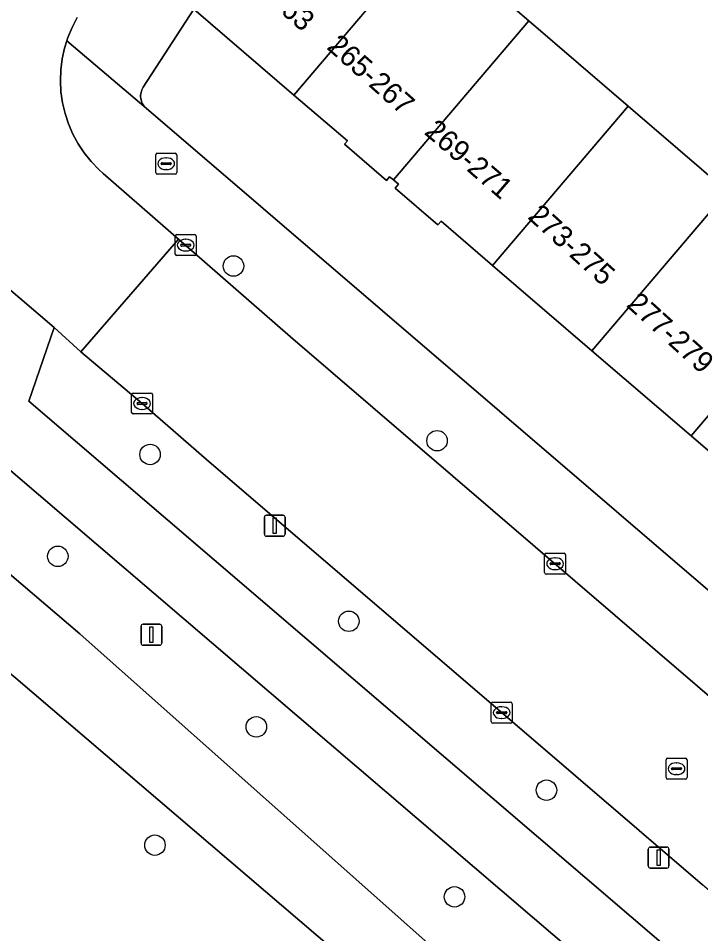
# Model space of a CAD drawing. Extents: x 159279 to 160377, y 384531 to 385888.
# Drawn here: x 159802.17 to 159834.73, y 384749.19 to 384792.89 of the extents above; entities that cross this region are included whole.
import ezdxf

# ---------------------------------------------------------------- set-up
doc = ezdxf.new("R2010")
doc.units = 0
for name, color, linetype in [('IMGEO_Berm_groen', 7, 'Continuous'), ('IMGEO_Boom', 7, 'Continuous'), ('IMGEO_Brandkraan', 7, 'Continuous'), ('IMGEO_Erf', 7, 'Continuous'), ('IMGEO_Fietspad_open', 7, 'Continuous'), ('IMGEO_Groenvoorziening', 7, 'Continuous'), ('IMGEO_Kolk', 7, 'Continuous'), ('IMGEO_Lichtmast', 7, 'Continuous'), ('IMGEO_Pand', 7, 'Continuous'), ('IMGEO_Pand_nummerreeks', 7, 'Continuous'), ('IMGEO_Rijbaan_lokaal_open', 7, 'Continuous'), ('IMGEO_Rioolput', 7, 'Continuous'), ('IMGEO_Voetpad_halfverhard', 7, 'Continuous'), ('IMGEO_Voetpad_open', 7, 'Continuous')]:
    doc.layers.add(name, color=color, linetype=linetype)

msp = doc.modelspace()

# ---------------------------------------------------------------- linework, layer by layer
at = {"layer": 'IMGEO_Berm_groen'}
for points in [[(159822.73, 384761.9), (159811.286, 384771.727), (159808.08, 384774.505), (159805.152, 384776.974), (159803.886, 384778.134), (159802.682, 384774.612), (159831.413, 384750), (159855.982, 384728.954), (159858.25, 384731.558), (159847.676, 384740.593), (159836.596, 384750), (159834.815, 384751.53)], [(159801.703, 384771.392), (159800.659, 384767.301), (159805.116, 384763.503), (159825.6, 384745.284), (159848.632, 384726.205), (159851.029, 384723.93), (159853.776, 384726.823), (159826.697, 384750)]]:
    msp.add_lwpolyline(points, close=True, dxfattribs=at)
at = {"layer": 'IMGEO_Boom'}
for centre in [(159812.439, 384781.067), (159822.155, 384772.728), (159808.461, 384772.07), (159804.058, 384767.208), (159817.943, 384764.108), (159813.53, 384759.068), (159827.376, 384756.044), (159808.692, 384753.42), (159822.989, 384750.954)]:
    msp.add_circle(centre, 0.489, dxfattribs=at)
at = {"layer": 'IMGEO_Brandkraan'}
for p, q in [((159808.73, 384785.526), (159808.73, 384786.378)), ((159808.805, 384786.452), (159809.657, 384786.452)), ((159809.218, 384786.232), (159809.243, 384786.232)), ((159809.731, 384786.378), (159809.731, 384785.526)), ((159808.989, 384785.946), (159808.989, 384785.958)), ((159809.427, 384785.909), (159809.029, 384785.909)), ((159809.032, 384785.995), (159809.43, 384785.995)), ((159809.473, 384785.958), (159809.473, 384785.946)), ((159809.657, 384785.452), (159808.805, 384785.452)), ((159809.241, 384785.672), (159809.216, 384785.672))]:
    msp.add_line(p, q, dxfattribs=at)
for points in [[(159808.73, 384785.526), (159808.73, 384786.378)], [(159808.805, 384786.452), (159809.657, 384786.452)], [(159809.731, 384786.378), (159809.731, 384785.526)], [(159809.657, 384785.452), (159808.805, 384785.452)]]:
    msp.add_lwpolyline(points, dxfattribs=at)
for centre, radius, start, end in [((159808.807, 384786.376), 0.0765, 91.552, 178.448), ((159808.807, 384786.376), 0.0765, 91.552, 178.448), ((159809.655, 384786.376), 0.0765, 1.552, 88.448), ((159809.655, 384786.376), 0.0765, 1.552, 88.448), ((159809.029, 384785.955), 0.0403, 85.8775, 175.7526), ((159809.026, 384785.945), 0.0366, 178.938, 274.7102), ((159809.43, 384785.952), 0.043, 264.8664, 352.4533), ((159809.434, 384785.957), 0.0386, 1.7309, 96.639), ((159808.807, 384785.528), 0.0765, 181.552, 268.448), ((159808.807, 384785.528), 0.0765, 181.552, 268.448), ((159809.655, 384785.528), 0.0765, 271.552, 358.448), ((159809.655, 384785.528), 0.0765, 271.552, 358.448)]:
    msp.add_arc(centre, radius, start, end, dxfattribs=at)
for centre, major_axis, ratio, start_param, end_param in [((159809.217, 384785.952), (-0.387, 0.002), 0.722429, 4.712389, 7.853982), ((159809.242, 384785.952), (-0.39, 0.002), 0.717154, 1.570796, 4.712389)]:
    msp.add_ellipse(centre, major_axis=major_axis, ratio=ratio, start_param=start_param, end_param=end_param, dxfattribs=at)
at = {"layer": 'IMGEO_Erf'}
for points in [[(159814.594, 384798.937), (159815.059, 384798.586), (159817.054, 384800.909), (159821.793, 384796.841), (159826.532, 384792.771), (159831.272, 384788.701), (159836.012, 384784.631), (159840.752, 384780.562), (159845.492, 384776.492), (159850.232, 384772.422), (159854.972, 384768.352), (159859.712, 384764.282), (159864.451, 384760.212), (159869.191, 384756.142), (159873.931, 384752.073), (159876.345, 384750), (159878.671, 384748.003), (159883.411, 384743.933), (159885.124, 384744.266), (159889.352, 384746.225), (159896.887, 384757.365), (159896.975, 384757.494), (159822.578, 384807.809)], [(159836.743, 384770.844), (159834.286, 384772.954), (159829.546, 384777.024), (159824.806, 384781.094), (159822.348, 384783.205), (159822.199, 384783.032), (159820.151, 384784.791), (159820.308, 384784.974), (159820.075, 384785.174), (159819.893, 384785.331), (159819.742, 384785.156), (159817.736, 384786.878), (159817.874, 384787.038), (159815.322, 384789.229), (159810.546, 384793.33), (159808.139, 384789.601), (159808.104, 384789.542), (159808.074, 384789.48), (159808.049, 384789.416), (159808.031, 384789.349), (159808.019, 384789.282), (159808.012, 384789.213), (159808.012, 384789.144), (159808.018, 384789.076), (159808.03, 384789.008), (159808.048, 384788.942), (159808.072, 384788.877), (159808.102, 384788.815), (159808.137, 384788.756), (159808.177, 384788.7), (159808.222, 384788.648), (159808.268, 384788.603), (159853.266, 384750)]]:
    msp.add_lwpolyline(points, dxfattribs=at)
at = {"layer": 'IMGEO_Fietspad_open'}
msp.add_lwpolyline([(159859.416, 384726.013), (159855.982, 384728.954), (159831.413, 384750), (159802.682, 384774.612), (159803.886, 384778.134), (159800.589, 384780.925), (159799.437, 384777.363), (159788.614, 384786.662), (159790.807, 384789.238), (159787.819, 384791.8), (159785.571, 384789.272), (159783.746, 384786.801), (159786.896, 384784.107), (159798.413, 384774.215), (159798.491, 384774.148), (159801.703, 384771.392), (159826.697, 384750), (159853.776, 384726.823), (159857.499, 384723.68)], dxfattribs=at)
at = {"layer": 'IMGEO_Groenvoorziening'}
msp.add_lwpolyline([(159845.317, 384724.65), (159823.259, 384743.264), (159802.05, 384761.39), (159798.105, 384764.665), (159786.804, 384735.881), (159794.418, 384727.063), (159801.729, 384733.387), (159801.507, 384733.655), (159805.787, 384737.392), (159806.023, 384737.131), (159813.731, 384743.883), (159824.896, 384730.93), (159824.445, 384730.535), (159827.058, 384727.504), (159827.511, 384727.898), (159837.427, 384716.393)], dxfattribs=at)
at = {"layer": 'IMGEO_Kolk'}
for p, q in [((159809.661, 384781.638), (159809.661, 384782.49)), ((159809.736, 384782.564), (159810.588, 384782.564)), ((159810.149, 384782.344), (159810.174, 384782.344)), ((159810.662, 384782.49), (159810.662, 384781.638)), ((159809.92, 384782.058), (159809.92, 384782.07)), ((159810.358, 384782.021), (159809.96, 384782.021)), ((159809.963, 384782.107), (159810.361, 384782.107)), ((159810.404, 384782.07), (159810.404, 384782.058)), ((159810.588, 384781.564), (159809.736, 384781.564)), ((159810.172, 384781.784), (159810.147, 384781.784)), ((159807.578, 384774.078), (159807.578, 384774.93)), ((159807.653, 384775.004), (159808.505, 384775.004)), ((159808.579, 384774.93), (159808.579, 384774.078)), ((159807.837, 384774.498), (159807.837, 384774.51)), ((159808.275, 384774.461), (159807.877, 384774.461)), ((159807.88, 384774.547), (159808.278, 384774.547)), ((159808.066, 384774.784), (159808.091, 384774.784)), ((159808.321, 384774.51), (159808.321, 384774.498)), ((159808.505, 384774.004), (159807.653, 384774.004)), ((159808.089, 384774.224), (159808.064, 384774.224)), ((159827.286, 384766.43), (159827.286, 384767.282)), ((159827.361, 384767.356), (159828.213, 384767.356)), ((159827.774, 384767.136), (159827.799, 384767.136)), ((159828.287, 384767.282), (159828.287, 384766.43)), ((159827.545, 384766.85), (159827.545, 384766.862)), ((159827.983, 384766.813), (159827.585, 384766.813)), ((159827.588, 384766.899), (159827.986, 384766.899)), ((159827.797, 384766.576), (159827.772, 384766.576)), ((159828.029, 384766.862), (159828.029, 384766.85)), ((159828.213, 384766.356), (159827.361, 384766.356)), ((159824.738, 384759.32), (159824.738, 384760.172)), ((159824.813, 384760.246), (159825.665, 384760.246)), ((159825.226, 384760.026), (159825.251, 384760.026)), ((159825.739, 384760.172), (159825.739, 384759.32)), ((159824.997, 384759.74), (159824.997, 384759.752)), ((159825.435, 384759.703), (159825.037, 384759.703)), ((159825.04, 384759.789), (159825.438, 384759.789)), ((159825.481, 384759.752), (159825.481, 384759.74)), ((159825.665, 384759.246), (159824.813, 384759.246)), ((159825.249, 384759.466), (159825.224, 384759.466))]:
    msp.add_line(p, q, dxfattribs=at)
for points in [[(159809.661, 384781.638), (159809.661, 384782.49)], [(159809.736, 384782.564), (159810.588, 384782.564)], [(159810.662, 384782.49), (159810.662, 384781.638)], [(159810.588, 384781.564), (159809.736, 384781.564)], [(159807.578, 384774.078), (159807.578, 384774.93)], [(159807.653, 384775.004), (159808.505, 384775.004)], [(159808.579, 384774.93), (159808.579, 384774.078)], [(159808.505, 384774.004), (159807.653, 384774.004)], [(159827.286, 384766.43), (159827.286, 384767.282)], [(159827.361, 384767.356), (159828.213, 384767.356)], [(159828.287, 384767.282), (159828.287, 384766.43)], [(159828.213, 384766.356), (159827.361, 384766.356)], [(159824.738, 384759.32), (159824.738, 384760.172)], [(159824.813, 384760.246), (159825.665, 384760.246)], [(159825.739, 384760.172), (159825.739, 384759.32)], [(159825.665, 384759.246), (159824.813, 384759.246)]]:
    msp.add_lwpolyline(points, dxfattribs=at)
for centre, radius, start, end in [((159809.738, 384782.488), 0.0765, 91.552, 178.448), ((159809.738, 384782.488), 0.0765, 91.552, 178.448), ((159810.586, 384782.488), 0.0765, 1.552, 88.448), ((159810.586, 384782.488), 0.0765, 1.552, 88.448), ((159809.96, 384782.067), 0.0403, 85.8775, 175.7526), ((159809.957, 384782.057), 0.0366, 178.938, 274.7102), ((159810.361, 384782.064), 0.043, 264.8664, 352.4533), ((159810.365, 384782.069), 0.0386, 1.7309, 96.639), ((159809.738, 384781.64), 0.0765, 181.552, 268.448), ((159809.738, 384781.64), 0.0765, 181.552, 268.448), ((159810.586, 384781.64), 0.0765, 271.552, 358.448), ((159810.586, 384781.64), 0.0765, 271.552, 358.448), ((159807.655, 384774.928), 0.0765, 91.552, 178.448), ((159807.655, 384774.928), 0.0765, 91.552, 178.448), ((159808.503, 384774.928), 0.0765, 1.552, 88.448), ((159808.503, 384774.928), 0.0765, 1.552, 88.448), ((159807.877, 384774.507), 0.0403, 85.8775, 175.7526), ((159807.874, 384774.497), 0.0366, 178.938, 274.7102), ((159808.278, 384774.504), 0.043, 264.8664, 352.4533), ((159808.282, 384774.509), 0.0386, 1.7309, 96.639), ((159807.655, 384774.08), 0.0765, 181.552, 268.448), ((159807.655, 384774.08), 0.0765, 181.552, 268.448), ((159808.503, 384774.08), 0.0765, 271.552, 358.448), ((159808.503, 384774.08), 0.0765, 271.552, 358.448), ((159827.363, 384767.28), 0.0765, 91.552, 178.448), ((159827.363, 384767.28), 0.0765, 91.552, 178.448), ((159828.211, 384767.28), 0.0765, 1.552, 88.448), ((159828.211, 384767.28), 0.0765, 1.552, 88.448), ((159827.585, 384766.859), 0.0403, 85.8775, 175.7526), ((159827.582, 384766.849), 0.0366, 178.938, 274.7102), ((159827.986, 384766.856), 0.043, 264.8664, 352.4533), ((159827.99, 384766.861), 0.0386, 1.7309, 96.639), ((159827.363, 384766.432), 0.0765, 181.552, 268.448), ((159827.363, 384766.432), 0.0765, 181.552, 268.448), ((159828.211, 384766.432), 0.0765, 271.552, 358.448), ((159828.211, 384766.432), 0.0765, 271.552, 358.448), ((159824.815, 384760.17), 0.0765, 91.552, 178.448), ((159824.815, 384760.17), 0.0765, 91.552, 178.448), ((159825.663, 384760.17), 0.0765, 1.552, 88.448), ((159825.663, 384760.17), 0.0765, 1.552, 88.448), ((159825.037, 384759.749), 0.0403, 85.8775, 175.7526), ((159825.034, 384759.739), 0.0366, 178.938, 274.7102), ((159825.438, 384759.746), 0.043, 264.8664, 352.4533), ((159825.442, 384759.751), 0.0386, 1.7309, 96.639), ((159824.815, 384759.322), 0.0765, 181.552, 268.448), ((159824.815, 384759.322), 0.0765, 181.552, 268.448), ((159825.663, 384759.322), 0.0765, 271.552, 358.448), ((159825.663, 384759.322), 0.0765, 271.552, 358.448)]:
    msp.add_arc(centre, radius, start, end, dxfattribs=at)
for centre, major_axis, ratio, start_param, end_param in [((159810.148, 384782.064), (-0.387, 0.002), 0.722429, 4.712389, 7.853982), ((159810.173, 384782.064), (-0.39, 0.002), 0.717154, 1.570796, 4.712389), ((159808.065, 384774.504), (-0.387, 0.002), 0.722429, 4.712389, 7.853982), ((159808.09, 384774.504), (-0.39, 0.002), 0.717154, 1.570796, 4.712389), ((159827.773, 384766.856), (-0.387, 0.002), 0.722429, 4.712389, 7.853982), ((159827.798, 384766.856), (-0.39, 0.002), 0.717154, 1.570796, 4.712389), ((159825.225, 384759.746), (-0.387, 0.002), 0.722429, 4.712389, 7.853982), ((159825.25, 384759.746), (-0.39, 0.002), 0.717154, 1.570796, 4.712389)]:
    msp.add_ellipse(centre, major_axis=major_axis, ratio=ratio, start_param=start_param, end_param=end_param, dxfattribs=at)
at = {"layer": 'IMGEO_Lichtmast'}
for p, q in [((159814.015, 384769.171), (159814.805, 384769.171)), ((159814.805, 384769.171), (159814.015, 384769.171)), ((159813.915, 384768.271), (159813.915, 384769.071)), ((159813.915, 384769.071), (159813.915, 384768.271)), ((159814.905, 384769.071), (159814.905, 384768.271)), ((159814.905, 384768.271), (159814.905, 384769.071)), ((159814.805, 384768.171), (159814.015, 384768.171)), ((159814.015, 384768.171), (159814.805, 384768.171)), ((159808.129, 384763.967), (159808.919, 384763.967)), ((159808.919, 384763.967), (159808.129, 384763.967)), ((159808.029, 384763.067), (159808.029, 384763.867)), ((159808.029, 384763.867), (159808.029, 384763.067)), ((159809.019, 384763.867), (159809.019, 384763.067)), ((159809.019, 384763.067), (159809.019, 384763.867)), ((159808.919, 384762.967), (159808.129, 384762.967)), ((159808.129, 384762.967), (159808.919, 384762.967)), ((159832.23, 384752.427), (159832.23, 384753.227)), ((159832.23, 384753.227), (159832.23, 384752.427)), ((159832.33, 384753.327), (159833.12, 384753.327)), ((159833.12, 384753.327), (159832.33, 384753.327)), ((159833.22, 384753.227), (159833.22, 384752.427)), ((159833.22, 384752.427), (159833.22, 384753.227)), ((159833.12, 384752.327), (159832.33, 384752.327)), ((159832.33, 384752.327), (159833.12, 384752.327))]:
    msp.add_line(p, q, dxfattribs=at)
for points in [[(159814.335, 384769.046), (159814.485, 384769.046), (159814.485, 384768.296), (159814.335, 384768.296), (159814.335, 384769.046)], [(159808.449, 384763.842), (159808.599, 384763.842), (159808.599, 384763.092), (159808.449, 384763.092), (159808.449, 384763.842)], [(159832.65, 384753.202), (159832.8, 384753.202), (159832.8, 384752.452), (159832.65, 384752.452), (159832.65, 384753.202)]]:
    msp.add_lwpolyline(points, dxfattribs=at)
for centre, start, end in [((159814.015, 384769.071), 90, 180), ((159814.015, 384769.071), 90, 180), ((159814.805, 384769.071), 0, 90), ((159814.805, 384769.071), 360, 90), ((159814.015, 384768.271), 180, 270), ((159814.015, 384768.271), 180, 270), ((159814.805, 384768.271), 270, 0), ((159814.805, 384768.271), 270, 0), ((159808.129, 384763.867), 90, 180), ((159808.129, 384763.867), 90, 180), ((159808.919, 384763.867), 0, 90), ((159808.919, 384763.867), 360, 90), ((159808.129, 384763.067), 180, 270), ((159808.129, 384763.067), 180, 270), ((159808.919, 384763.067), 270, 0), ((159808.919, 384763.067), 270, 0), ((159832.33, 384753.227), 90, 180), ((159832.33, 384753.227), 90, 180), ((159833.12, 384753.227), 0, 90), ((159833.12, 384753.227), 360, 90), ((159832.33, 384752.427), 180, 270), ((159832.33, 384752.427), 180, 270), ((159833.12, 384752.427), 270, 0), ((159833.12, 384752.427), 270, 0)]:
    msp.add_arc(centre, 0.1, start, end, dxfattribs=at)
at = {"layer": 'IMGEO_Pand'}
for points in [[(159815.322, 384789.229), (159821.793, 384796.841), (159817.054, 384800.909), (159815.059, 384798.586), (159810.546, 384793.33)], [(159817.874, 384787.038), (159817.736, 384786.878), (159819.742, 384785.156), (159819.893, 384785.331), (159820.075, 384785.174), (159826.532, 384792.771), (159821.793, 384796.841), (159815.322, 384789.229)], [(159826.532, 384792.771), (159820.075, 384785.174), (159820.308, 384784.974), (159820.151, 384784.791), (159822.199, 384783.032), (159822.348, 384783.205), (159824.806, 384781.094), (159831.272, 384788.701)], [(159829.546, 384777.024), (159836.012, 384784.631), (159831.272, 384788.701), (159824.806, 384781.094)], [(159836.012, 384784.631), (159829.546, 384777.024), (159834.286, 384772.954), (159840.752, 384780.562)], [(159840.752, 384780.562), (159834.286, 384772.954), (159836.743, 384770.844), (159836.604, 384770.683), (159838.626, 384768.947), (159838.763, 384769.107), (159839.024, 384768.882), (159845.492, 384776.492)]]:
    msp.add_lwpolyline(points, close=True, dxfattribs=at)
at = {"layer": 'IMGEO_Rijbaan_lokaal_open'}
for points in [[(159800.589, 384780.925), (159803.886, 384778.134), (159805.152, 384776.974), (159809.818, 384782.351), (159806.227, 384785.489), (159806.016, 384785.68), (159805.651, 384786.059), (159805.321, 384786.469), (159805.029, 384786.907), (159804.777, 384787.369), (159804.567, 384787.852), (159804.402, 384788.352), (159804.282, 384788.864), (159804.208, 384789.385), (159804.181, 384789.911), (159804.201, 384790.437), (159804.267, 384790.959), (159804.381, 384791.473), (159804.488, 384791.813), (159804.539, 384791.975), (159804.742, 384792.461), (159804.988, 384792.926)], [(159836.494, 384759.376), (159815.158, 384777.694), (159809.818, 384782.351), (159805.152, 384776.974), (159808.08, 384774.505), (159811.286, 384771.727), (159822.73, 384761.9), (159834.815, 384751.53)]]:
    msp.add_lwpolyline(points, dxfattribs=at)
at = {"layer": 'IMGEO_Rioolput'}
for p, q in [((159833.083, 384756.643), (159833.083, 384757.495)), ((159833.158, 384757.569), (159834.01, 384757.569)), ((159833.571, 384757.349), (159833.596, 384757.349)), ((159834.084, 384757.495), (159834.084, 384756.643)), ((159833.342, 384757.063), (159833.342, 384757.075)), ((159833.78, 384757.026), (159833.382, 384757.026)), ((159833.385, 384757.112), (159833.783, 384757.112)), ((159833.826, 384757.075), (159833.826, 384757.063)), ((159834.01, 384756.569), (159833.158, 384756.569)), ((159833.594, 384756.789), (159833.569, 384756.789))]:
    msp.add_line(p, q, dxfattribs=at)
for points in [[(159833.083, 384756.643), (159833.083, 384757.495)], [(159833.158, 384757.569), (159834.01, 384757.569)], [(159834.084, 384757.495), (159834.084, 384756.643)], [(159834.01, 384756.569), (159833.158, 384756.569)]]:
    msp.add_lwpolyline(points, dxfattribs=at)
for centre, radius, start, end in [((159833.16, 384757.493), 0.0765, 91.552, 178.448), ((159833.16, 384757.493), 0.0765, 91.552, 178.448), ((159834.008, 384757.493), 0.0765, 1.552, 88.448), ((159834.008, 384757.493), 0.0765, 1.552, 88.448), ((159833.382, 384757.072), 0.0403, 85.8775, 175.7526), ((159833.379, 384757.062), 0.0366, 178.938, 274.7102), ((159833.783, 384757.069), 0.043, 264.8664, 352.4533), ((159833.787, 384757.074), 0.0386, 1.7309, 96.639), ((159833.16, 384756.645), 0.0765, 181.552, 268.448), ((159833.16, 384756.645), 0.0765, 181.552, 268.448), ((159834.008, 384756.645), 0.0765, 271.552, 358.448), ((159834.008, 384756.645), 0.0765, 271.552, 358.448)]:
    msp.add_arc(centre, radius, start, end, dxfattribs=at)
for centre, major_axis, ratio, start_param, end_param in [((159833.57, 384757.069), (-0.387, 0.002), 0.722429, 4.712389, 7.853982), ((159833.595, 384757.069), (-0.39, 0.002), 0.717154, 1.570796, 4.712389)]:
    msp.add_ellipse(centre, major_axis=major_axis, ratio=ratio, start_param=start_param, end_param=end_param, dxfattribs=at)
at = {"layer": 'IMGEO_Voetpad_halfverhard'}
for points in [[(159800.659, 384767.301), (159801.703, 384771.392), (159798.491, 384774.148), (159797.174, 384770.201), (159784.132, 384780.794), (159786.896, 384784.107), (159783.746, 384786.801), (159781.425, 384784.027), (159778.947, 384781.17), (159785.569, 384775.426), (159795.704, 384767.116), (159796.656, 384766.335), (159798.105, 384764.665), (159802.05, 384761.39), (159823.259, 384743.264), (159845.317, 384724.65), (159849.834, 384720.526), (159852.296, 384718.633), (159866.495, 384706.815)], [(159871.726, 384706.336), (159854.968, 384720.449), (159857.499, 384723.68), (159853.776, 384726.823), (159851.029, 384723.93), (159848.632, 384726.205), (159825.6, 384745.284), (159805.116, 384763.503), (159800.659, 384767.301)]]:
    msp.add_lwpolyline(points, dxfattribs=at)
at = {"layer": 'IMGEO_Voetpad_open'}
for points in [[(159804.988, 384792.926), (159804.742, 384792.461), (159804.539, 384791.975), (159804.488, 384791.813), (159808.268, 384788.603), (159808.222, 384788.648), (159808.177, 384788.7), (159808.137, 384788.756), (159808.102, 384788.815), (159808.072, 384788.877), (159808.048, 384788.942), (159808.03, 384789.008), (159808.018, 384789.076), (159808.012, 384789.144), (159808.012, 384789.213), (159808.019, 384789.282), (159808.031, 384789.349), (159808.049, 384789.416), (159808.074, 384789.48), (159808.104, 384789.542), (159808.139, 384789.601), (159810.546, 384793.33)], [(159853.266, 384750), (159808.268, 384788.603), (159804.488, 384791.813), (159804.381, 384791.473), (159804.267, 384790.959), (159804.201, 384790.437), (159804.181, 384789.911), (159804.208, 384789.385), (159804.282, 384788.864), (159804.402, 384788.352), (159804.567, 384787.852), (159804.777, 384787.369), (159805.029, 384786.907), (159805.321, 384786.469), (159805.651, 384786.059), (159806.016, 384785.68), (159806.227, 384785.489), (159809.818, 384782.351), (159815.158, 384777.694), (159836.494, 384759.376)]]:
    msp.add_lwpolyline(points, dxfattribs=at)

# ---------------------------------------------------------------- texts
at = {"layer": 'IMGEO_Pand_nummerreeks'}
for s, rotation, p in [('261-263', 318.8158, (159812.056, 384795.445)), ('265-267', 318.3689, (159816.844, 384791.471)), ('269-271', 319.2512, (159821.499, 384787.401)), ('273-275', 317.8131, (159826.433, 384783.368)), ('277-279', 317.9105, (159831.145, 384779.164))]:
    msp.add_text(s, height=1, rotation=rotation, dxfattribs=at).set_placement(p)

doc.saveas('drawing.dxf')
